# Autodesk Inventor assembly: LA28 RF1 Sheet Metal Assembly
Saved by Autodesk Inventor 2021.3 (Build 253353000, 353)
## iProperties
Created: 2023-01
Part Number: LA28 RF1 Sheet Metal Assembly
Document SubType Name: Assembly
Designer: AdminForWorker
Title: LA28 RF1 Sheet Metal Assembly v3
Author: AdminForWorker
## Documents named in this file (8)
- c:\worker\convert-fusion-r08-cosv3\tmp\job-1\7\output\files\23b6ab5d-c720-4e55-9879-a23ce6995bc1\LA28 RF1 Sheet Metal Assembly v3.iam
- c:\worker\convert-fusion-r08-cosv3\tmp\job-1\7\output\files\23b6ab5d-c720-4e55-9879-a23ce6995bc1\LA28RF1 Front Rear C Channel^la28RF1 SHEET METAL ASSEMBLY.ipt
- c:\worker\convert-fusion-r08-cosv3\tmp\job-1\7\output\files\23b6ab5d-c720-4e55-9879-a23ce6995bc1\LA28RF1 Center Bar^la28RF1 SHEET METAL ASSEMBLY.ipt
- c:\worker\convert-fusion-r08-cosv3\tmp\job-1\7\output\files\23b6ab5d-c720-4e55-9879-a23ce6995bc1\AL28RF1 Outer Bar^la28RF1 SHEET METAL ASSEMBLY.ipt
- c:\worker\convert-fusion-r08-cosv3\tmp\job-1\7\output\files\23b6ab5d-c720-4e55-9879-a23ce6995bc1\Inclinometer Mount Plate^la28RF1 SHEET METAL ASSEMBLY.ipt
- c:\worker\convert-fusion-r08-cosv3\tmp\job-1\7\output\files\23b6ab5d-c720-4e55-9879-a23ce6995bc1\Stabilizing Tube^la28RF1 SHEET METAL ASSEMBLY.ipt
- c:\worker\convert-fusion-r08-cosv3\tmp\job-1\7\output\files\23b6ab5d-c720-4e55-9879-a23ce6995bc1\Rear Connection Arm^la28RF1 SHEET METAL ASSEMBLY.ipt
- c:\worker\convert-fusion-r08-cosv3\tmp\job-1\7\output\files\23b6ab5d-c720-4e55-9879-a23ce6995bc1\LA18 LA28 Front Connection Tongue^la28RF1 SHEET METAL ASSEMBLY.ipt
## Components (15 placed, 7 different names)
1. LA28RF1 Front Rear C Channel^la28RF1 SHEET METAL ASSEMBLY:1
2. LA28RF1 Front Rear C Channel^la28RF1 SHEET METAL ASSEMBLY:2
3. LA28RF1 Center Bar^la28RF1 SHEET METAL ASSEMBLY:1
4. LA28RF1 Center Bar^la28RF1 SHEET METAL ASSEMBLY:2
5. AL28RF1 Outer Bar^la28RF1 SHEET METAL ASSEMBLY:1
6. AL28RF1 Outer Bar^la28RF1 SHEET METAL ASSEMBLY:2
7. AL28RF1 Outer Bar^la28RF1 SHEET METAL ASSEMBLY:3
8. AL28RF1 Outer Bar^la28RF1 SHEET METAL ASSEMBLY:4
9. Inclinometer Mount Plate^la28RF1 SHEET METAL ASSEMBLY:1
10. Stabilizing Tube^la28RF1 SHEET METAL ASSEMBLY:1
11. Stabilizing Tube^la28RF1 SHEET METAL ASSEMBLY:2
12. Rear Connection Arm^la28RF1 SHEET METAL ASSEMBLY:1
13. Rear Connection Arm^la28RF1 SHEET METAL ASSEMBLY:2
14. LA18 LA28 Front Connection Tongue^la28RF1 SHEET METAL ASSEMBLY:1
15. LA18 LA28 Front Connection Tongue^la28RF1 SHEET METAL ASSEMBLY:2
